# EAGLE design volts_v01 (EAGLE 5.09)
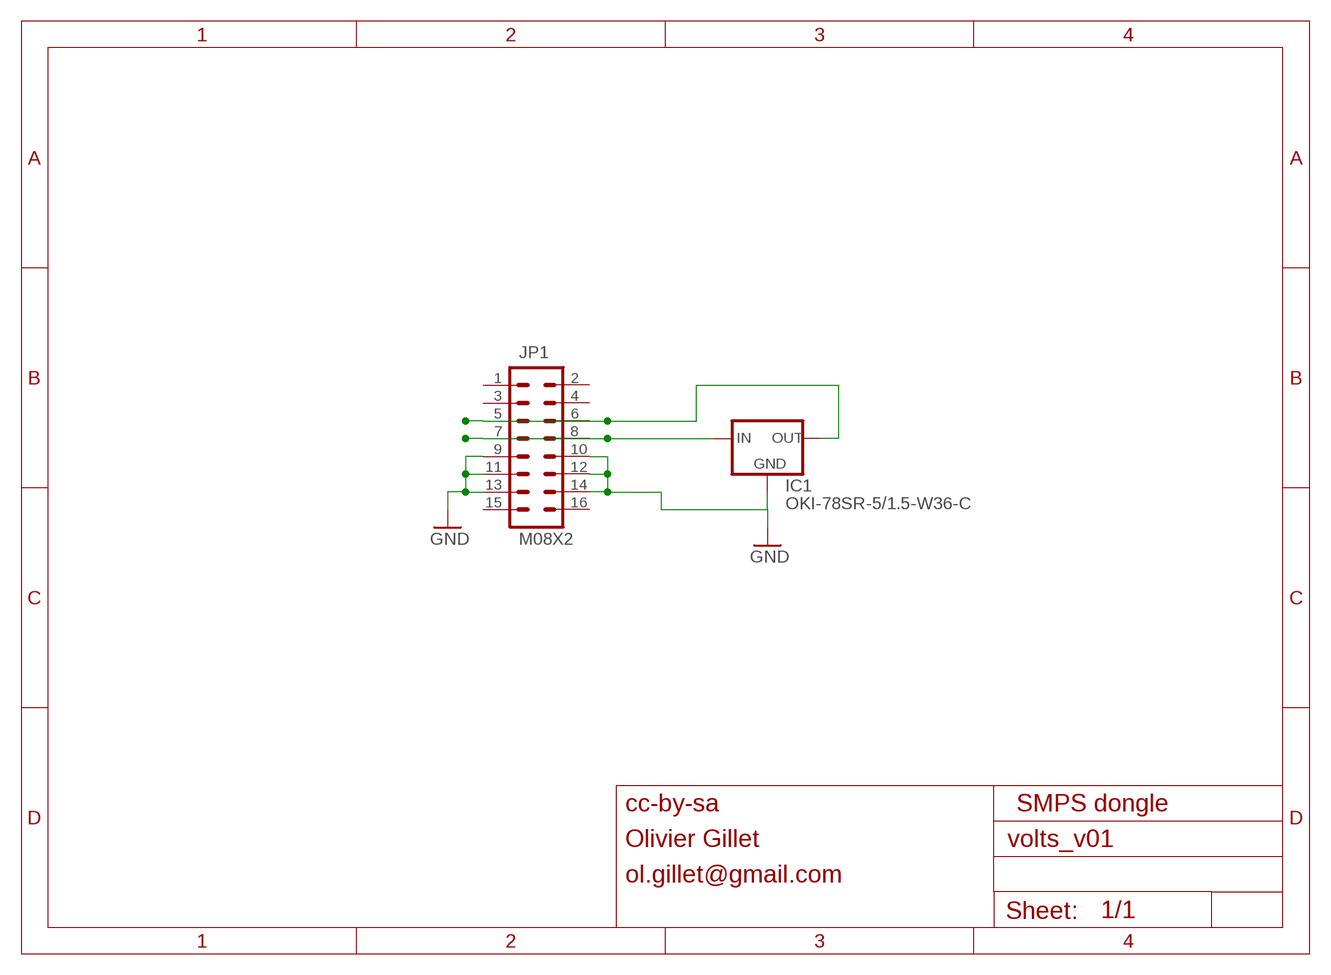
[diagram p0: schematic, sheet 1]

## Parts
IC1  OKI-78SR-5/1.5-W36-C  OKI-78SR  [OKI78SR]
JP1  M08X2  [2X8]

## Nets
GND: IC1.2(GND) JP1.9 JP1.10 JP1.11 JP1.12 JP1.13 JP1.14
N$1: IC1.1(IN) JP1.7 JP1.8
N$2: IC1.3(OUT) JP1.5 JP1.6
Unconnected: JP1.1 JP1.2 JP1.3 JP1.4 JP1.15 JP1.16

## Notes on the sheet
- cc-by-sa | SMPS dongle
- Olivier Gillet
- ol.gillet@gmail.com

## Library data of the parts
IC1 = og-vreg:OKI-78SR
JP1 = SparkFun:M08X2

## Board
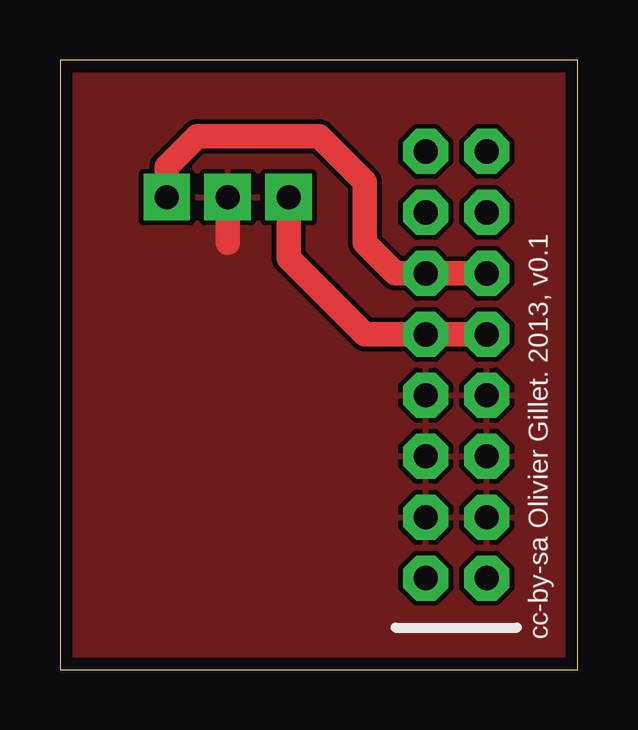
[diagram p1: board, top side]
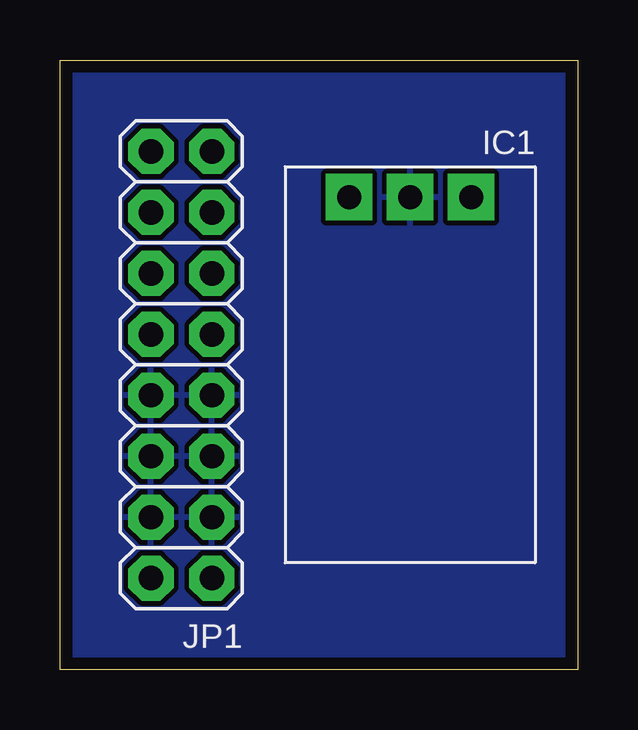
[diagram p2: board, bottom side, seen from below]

Size 21.57 x 25.4 mm. Coordinates in mm from the lower left corner, seen from the top.
Outline: 0,0 21.57,0 21.57,25.4 0,25.4 0,0
Copper layers (1*16): Top 0.035mm / dielectric 1.5mm / Bottom 0.035mm
Design rules "PCBCart-Standard *": minimum track width 8mil, minimum drill 0.4mm, track to track 8mil, track to pad 8mil, pad to pad 8mil, via to via 8mil, smd to smd 8mil, copper to edge 20mil, drill to drill 8mil, minimum pad ring 8mil, minimum via ring 10mil, stop-mask expansion 3mil, vias tented up to drill 0mil, thermal gap 8mil

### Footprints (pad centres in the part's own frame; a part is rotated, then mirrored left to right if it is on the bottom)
OKI78SR = drill 1 pad 1.93 square: 1 2.54,0; 2 0,0; 3 -2.54,0
2X8 = drill 1.016 pad 1.88 octagon: 1 0,0; 2 0,2.54; 3 2.54,0; 4 2.54,2.54; 5 5.08,0; 6 5.08,2.54; 7 7.62,0; 8 7.62,2.54; 9 10.16,0; 10 10.16,2.54; 11 12.7,0; 12 12.7,2.54; 13 15.24,0; 14 15.24,2.54; 15 17.78,0; 16 17.78,2.54

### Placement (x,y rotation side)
IC1  6.99,19.68 180 bottom
JP1  17.78,21.59 270 bottom
U$1  [LOGO_5VOLTS]  1.11,0.48 0 top
U$2  [LOGO_5VOLTS_EDIT]  1.91,11.43 0 top

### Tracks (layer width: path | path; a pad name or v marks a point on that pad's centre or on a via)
GND
  Top 1.016: IC1.2 6.99,17.78
  pour Top: 0,25.4 0,0 21.59,0 21.59,25.4
  pour Bottom: 0,25.4 0,0 21.59,0 21.59,25.4
N$1
  Top 1.016: IC1.1 9.53,17.14 12.7,13.97 JP1.8 JP1.7
N$2
  Top 1.016: IC1.3 4.45,20.95 5.71,22.23 10.79,22.23 12.7,20.32 12.7,17.78 13.97,16.51 JP1.6 JP1.5

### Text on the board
tNames: cc-by-sa Olivier Gillet. 2013, v0.1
